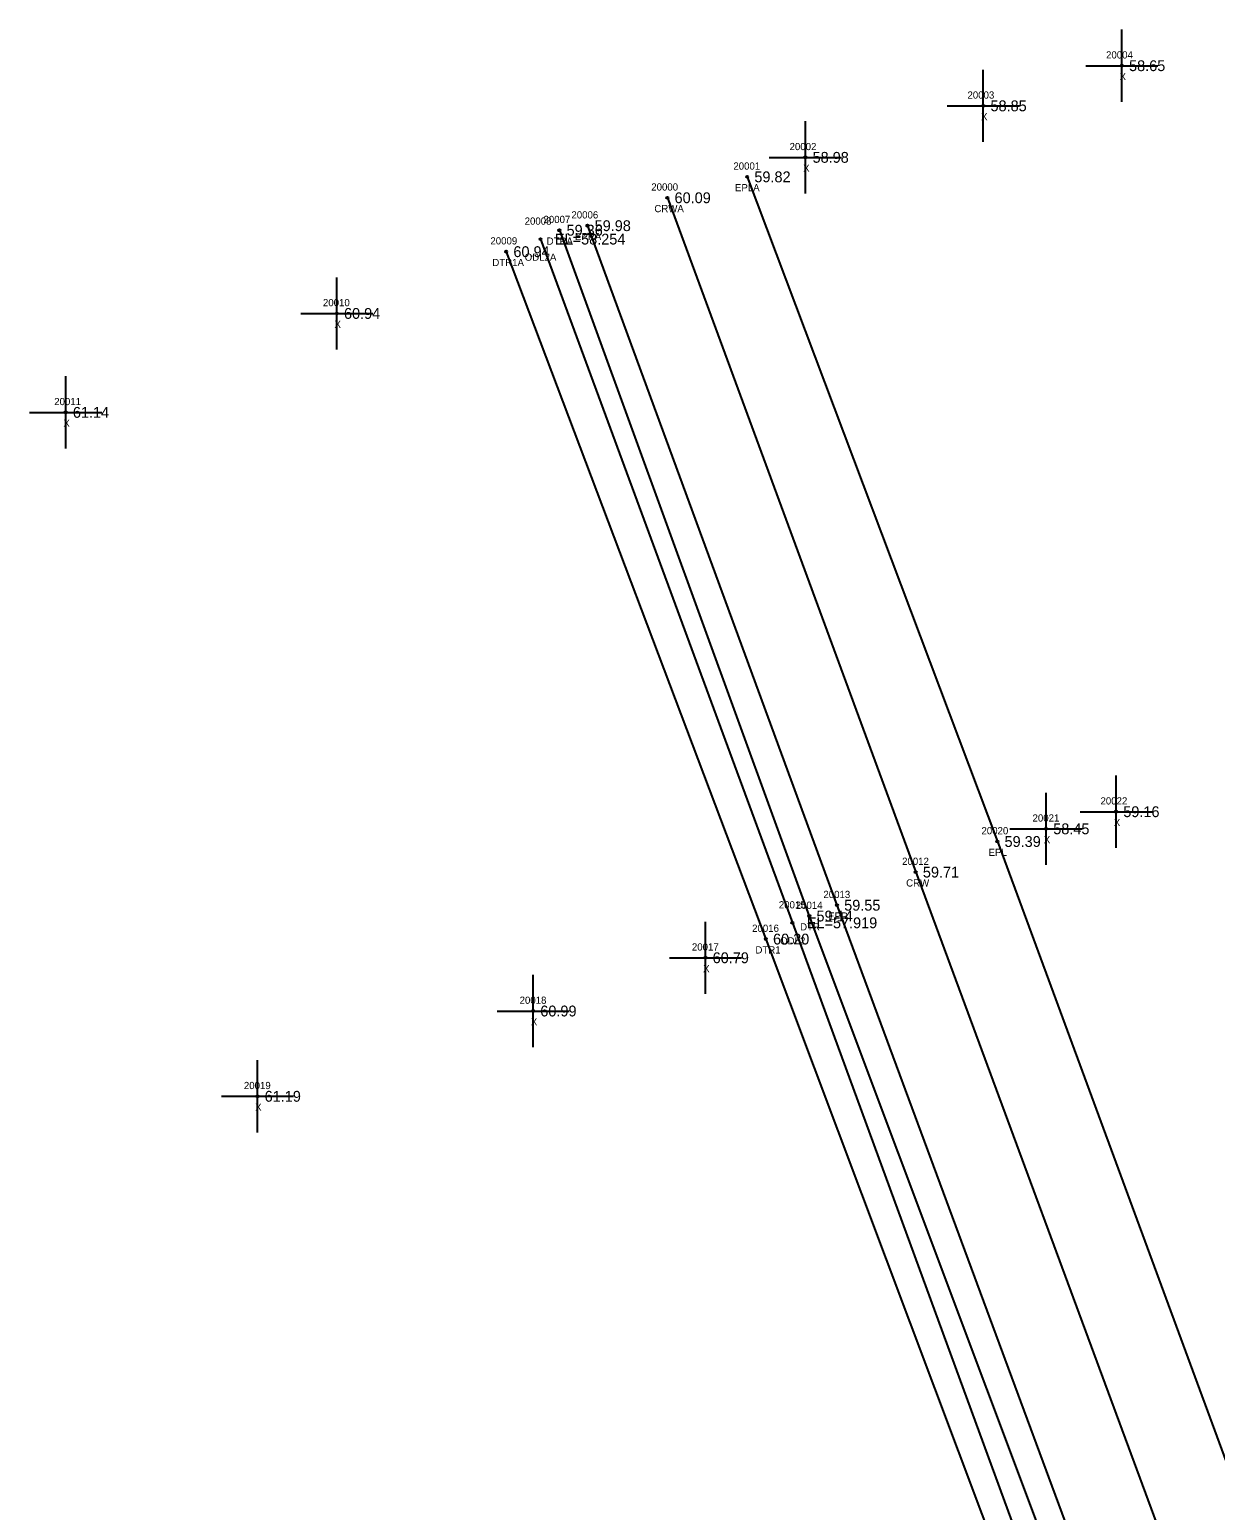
# Model space of a CAD drawing. Extents: x 2396547 to 2397655, y 770185 to 772649.
# Drawn here: x 2396581.5 to 2396745.8, y 772433 to 772638.2 of the extents above; entities that cross this region are included whole.
import ezdxf

# ---------------------------------------------------------------- set-up
doc = ezdxf.new("R2010")
doc.units = 0
for name, color, linetype in [('RD_DTM_BkLn1', 7, 'Continuous'), ('RD_EX_H2O', 7, 'Continuous'), ('RD_EX_H2O_txCode', 7, 'Continuous'), ('RD_EX_Misc', 7, 'Continuous'), ('RD_EX_Misc_txCode', 7, 'Continuous'), ('RD_EX_Road', 7, 'Continuous'), ('RD_EX_Road_txCode', 7, 'Continuous'), ('RD_EX_TX_H2O_ELEV', 7, 'Continuous'), ('RD_EX_TX_Misc_ELEV', 7, 'Continuous'), ('RD_EX_TX_Road_ELEV', 7, 'Continuous'), ('RD_HC_Survey_ELEV', 7, 'Continuous'), ('RD_HC_Survey_txCode', 7, 'Continuous'), ('RD_SMD_Locator', 7, 'Continuous')]:
    doc.layers.add(name, color=color, linetype=linetype)

msp = doc.modelspace()

# ---------------------------------------------------------------- linework, layer by layer
at = {"layer": 'RD_DTM_BkLn1'}
msp.add_lwpolyline([(2396669.86, 772614.94), (2396704.28, 772521.49), (2396739.29, 772426.89), (2396775.36, 772328.69), (2396800.21, 772259.35), (2396825.58, 772185.8), (2396852.46, 772104.52), (2396872.48, 772041.55), (2396897.57, 771959.72), (2396918.76, 771888.68), (2396939.09, 771818.34), (2396959.29, 771747.62), (2396993.72, 771617.68), (2397022.56, 771506.67), (2397049.1, 771404.69)], dxfattribs=at)
at = {"layer": 'RD_EX_H2O'}
for points in [[(2396654.89, 772610.44), (2396689.53, 772515.4), (2396726.4, 772417.15), (2396758.49, 772332.26), (2396786.59, 772254.26)], [(2396647.52, 772607.47), (2396683.51, 772512.21), (2396720.14, 772414.69), (2396752.02, 772329.6), (2396778.94, 772251.31)], [(2396652.28, 772609.21), (2396687.19, 772514.46), (2396723.26, 772416.1), (2396755.2, 772330.94), (2396781.71, 772252.52)]]:
    msp.add_lwpolyline(points, dxfattribs=at)
at = {"layer": 'RD_EX_Misc'}
for p, q in [((2396732.86, 772628.24), (2396732.86, 772638.24)), ((2396713.65, 772622.68), (2396713.65, 772632.68)), ((2396727.86, 772633.24), (2396737.86, 772633.24)), ((2396708.65, 772627.68), (2396718.65, 772627.68)), ((2396688.99, 772615.54), (2396688.99, 772625.54)), ((2396683.99, 772620.54), (2396693.99, 772620.54)), ((2396624.04, 772593.91), (2396624.04, 772603.91)), ((2396619.04, 772598.91), (2396629.04, 772598.91)), ((2396586.46, 772580.2), (2396586.46, 772590.2)), ((2396581.46, 772585.2), (2396591.46, 772585.2)), ((2396732.06, 772524.86), (2396732.06, 772534.86)), ((2396722.35, 772522.49), (2396722.35, 772532.49)), ((2396727.06, 772529.86), (2396737.06, 772529.86)), ((2396717.35, 772527.49), (2396727.35, 772527.49)), ((2396675.14, 772504.62), (2396675.14, 772514.62)), ((2396670.14, 772509.62), (2396680.14, 772509.62)), ((2396651.25, 772497.24), (2396651.25, 772507.24)), ((2396646.25, 772502.24), (2396656.25, 772502.24)), ((2396613.04, 772485.42), (2396613.04, 772495.42)), ((2396608.04, 772490.42), (2396618.04, 772490.42))]:
    msp.add_line(p, q, dxfattribs=at)
at = {"layer": 'RD_EX_Road'}
for points in [[(2396680.92, 772617.84), (2396715.6, 772525.73), (2396750.68, 772430.62), (2396786.3, 772332.21), (2396811.38, 772263.31), (2396839.69, 772181.74), (2396863.75, 772109.83), (2396883.63, 772046.56), (2396889.54, 772027.11), (2396896.25, 772004.37), (2396904.34, 771978.33), (2396908.24, 771964.89), (2396921.74, 771919.68), (2396927.03, 771902.11), (2396950.2, 771821.74), (2396970.47, 771750.68), (2396978.33, 771721.29), (2396990.58, 771675.04), (2397004.94, 771620.49), (2397034.26, 771508.8), (2397061.11, 771410.49), (2397060.64, 771407.04), (2397062.07, 771407.67)], [(2396658.78, 772611.07), (2396693.37, 772516.9), (2396729.65, 772418.78), (2396760.7, 772333.11), (2396788.58, 772254.87), (2396814.65, 772181.57), (2396841.1, 772100.86), (2396861.19, 772037.76), (2396886.09, 771955.71), (2396907.15, 771884.49), (2396928.56, 771811.72), (2396947.65, 771744.09), (2396985.17, 771602.64), (2397011.11, 771504.04), (2397037.95, 771404.25), (2397039, 771401.22)]]:
    msp.add_lwpolyline(points, dxfattribs=at)
at = {"layer": 'RD_SMD_Locator'}
for centre in [(2396732.86, 772633.24), (2396713.65, 772627.68), (2396688.99, 772620.54), (2396680.92, 772617.84), (2396669.86, 772614.94), (2396654.89, 772610.44), (2396658.78, 772611.07), (2396647.52, 772607.47), (2396652.28, 772609.21), (2396624.04, 772598.91), (2396586.46, 772585.2), (2396732.06, 772529.86), (2396722.35, 772527.49), (2396715.6, 772525.73), (2396704.28, 772521.49), (2396689.53, 772515.4), (2396693.37, 772516.9), (2396687.19, 772514.46), (2396683.51, 772512.21), (2396675.14, 772509.62), (2396651.25, 772502.24), (2396613.04, 772490.42)]:
    msp.add_circle(centre, 0.15, dxfattribs=at)

# ---------------------------------------------------------------- texts
at = {"layer": 'RD_EX_H2O_txCode'}
for s, p in [('20008', (2396650.08, 772611.21)), ('20007', (2396652.69, 772611.44)), ('20009', (2396645.33, 772608.47)), ('DTRA', (2396653.13, 772608.44)), ('DTR1A', (2396645.6, 772605.47)), ('ODL2A', (2396650.09, 772606.21)), ('20015', (2396685.31, 772516.46)), ('20014', (2396687.66, 772516.4)), ('20016', (2396681.61, 772513.21)), ('DTR', (2396688.26, 772513.4)), ('DTR1', (2396682.07, 772510.21)), ('ODL2', (2396685.49, 772511.46))]:
    msp.add_text(s, height=1, dxfattribs=at).set_placement(p)
at = {"layer": 'RD_EX_Misc_txCode'}
for s, p in [('20004', (2396730.67, 772634.24)), ('X', (2396732.55, 772631.24)), ('20003', (2396711.46, 772628.68)), ('X', (2396713.34, 772625.68)), ('20002', (2396686.8, 772621.54)), ('X', (2396688.68, 772618.54)), ('20010', (2396622.12, 772599.91)), ('X', (2396623.72, 772596.91)), ('20011', (2396584.87, 772586.2)), ('X', (2396586.14, 772583.2)), ('20022', (2396729.9, 772530.86)), ('20021', (2396720.48, 772528.49)), ('X', (2396731.75, 772527.86)), ('X', (2396722.04, 772525.49)), ('20017', (2396673.26, 772510.62)), ('X', (2396674.82, 772507.62)), ('20018', (2396649.38, 772503.24)), ('X', (2396650.94, 772500.24)), ('20019', (2396611.16, 772491.42)), ('X', (2396612.72, 772488.42))]:
    msp.add_text(s, height=1, dxfattribs=at).set_placement(p)
at = {"layer": 'RD_EX_Road_txCode'}
for s, p in [('20001', (2396679.01, 772618.84)), ('EPLA', (2396679.23, 772615.84)), ('20006', (2396656.56, 772612.07)), ('EPRA', (2396657.06, 772609.07)), ('20020', (2396713.4, 772526.73)), ('EPL', (2396714.39, 772523.73)), ('20013', (2396691.49, 772517.9)), ('EPR', (2396692.14, 772514.9))]:
    msp.add_text(s, height=1, dxfattribs=at).set_placement(p)
at = {"layer": 'RD_EX_TX_H2O_ELEV'}
for s, p in [('EL=58.254', (2396654.28, 772608.46)), ('59.36', (2396655.89, 772609.69)), ('60.94', (2396648.52, 772606.72)), ('EL=57.919', (2396689.19, 772513.71)), ('59.14', (2396690.53, 772514.65)), ('60.20', (2396684.51, 772511.46))]:
    msp.add_text(s, height=1.5, dxfattribs=at).set_placement(p)
at = {"layer": 'RD_EX_TX_Misc_ELEV'}
for s, p in [('58.65', (2396733.86, 772632.49)), ('58.85', (2396714.65, 772626.93)), ('58.98', (2396689.99, 772619.79)), ('60.94', (2396625.04, 772598.16)), ('61.14', (2396587.46, 772584.45)), ('59.16', (2396733.06, 772529.11)), ('58.45', (2396723.35, 772526.74)), ('60.79', (2396676.14, 772508.87)), ('60.99', (2396652.25, 772501.49)), ('61.19', (2396614.04, 772489.67))]:
    msp.add_text(s, height=1.5, dxfattribs=at).set_placement(p)
at = {"layer": 'RD_EX_TX_Road_ELEV'}
for s, p in [('59.82', (2396681.92, 772617.09)), ('59.98', (2396659.78, 772610.32)), ('59.39', (2396716.6, 772524.98)), ('59.55', (2396694.37, 772516.15))]:
    msp.add_text(s, height=1.5, dxfattribs=at).set_placement(p)
at = {"layer": 'RD_HC_Survey_ELEV'}
for s, p in [('60.09', (2396670.86, 772614.19)), ('59.71', (2396705.28, 772520.74))]:
    msp.add_text(s, height=1.5, dxfattribs=at).set_placement(p)
at = {"layer": 'RD_HC_Survey_txCode'}
for s, p in [('20000', (2396667.63, 772615.94)), ('CRWA', (2396668.06, 772612.94)), ('20012', (2396702.4, 772522.49)), ('CRW', (2396702.96, 772519.49))]:
    msp.add_text(s, height=1, dxfattribs=at).set_placement(p)

doc.saveas('drawing.dxf')
